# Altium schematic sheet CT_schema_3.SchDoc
size 313 x 200 mm
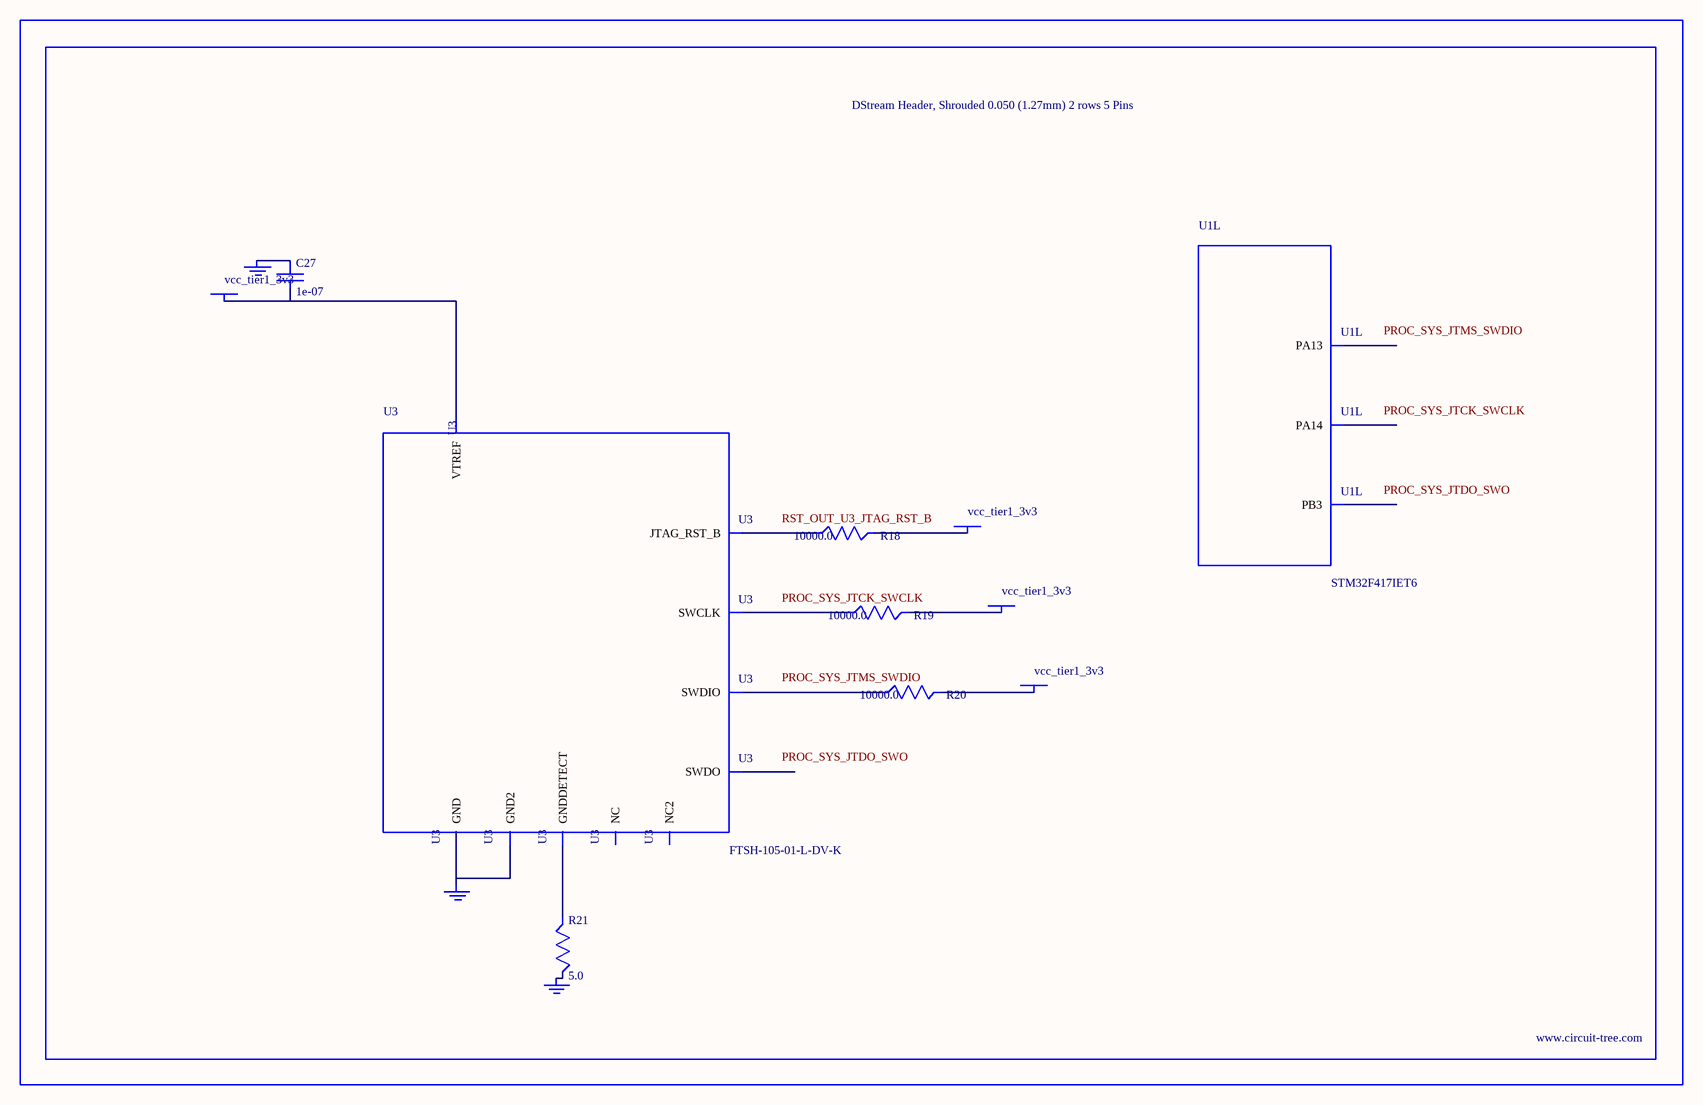
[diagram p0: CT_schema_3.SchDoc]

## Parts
BORDER2  (no value)
C27  1e-07  [C0402]
GND_INSTANCE_2_0  (no value)
GND_INSTANCE_2_1  (no value)
GND_INSTANCE_2_2  (no value)
POWER_INSTANCE_2_0  vcc_tier1_3v3
POWER_INSTANCE_2_1  vcc_tier1_3v3
POWER_INSTANCE_2_2  vcc_tier1_3v3
POWER_INSTANCE_2_3  vcc_tier1_3v3
R18  10000.0  [R0603]
R19  10000.0  [R0603]
R20  10000.0  [R0603]
R21  5.0  [R0603]
U1  STM32F417IET6  [LQFP176]  (part L of 14)
U3  FTSH-105-01-L-DV-K  [SAMTEC_FTSH-105-01-L-DV-K]

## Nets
NetC27_1: C27.1 GND_INSTANCE_2_0.0(GND)
NetC27_2: C27.2 POWER_INSTANCE_2_0.0(PWR) U3.1(VTREF)
NetGND_INSTANCE_2_1_0: GND_INSTANCE_2_1.0(GND) R21.2
NetGND_INSTANCE_2_2_0: GND_INSTANCE_2_2.0(GND) U3.3(GND) U3.5(GND2)
NetPOWER_INSTANCE_2_1_0: POWER_INSTANCE_2_1.0(PWR) R20.2
NetPOWER_INSTANCE_2_2_0: POWER_INSTANCE_2_2.0(PWR) R19.2
NetPOWER_INSTANCE_2_3_0: POWER_INSTANCE_2_3.0(PWR) R18.2
NetR18_1: R18.1 U3.10(JTAG_RST_B)
NetR19_1: R19.1 U3.4(SWCLK)
NetR20_1: R20.1 U3.2(SWDIO)
NetR21_1: R21.1 U3.9(GNDDETECT)

Not connected (* = marked no-connect by the designer): U1 124(PA13) 137(PA14) 161(PB3); U3 6(SWDO) 7(NC) 8(NC2)

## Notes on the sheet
- Labels drawn without touching a wire or pin: PROC_SYS_JTCK_SWCLK, PROC_SYS_JTDO_SWO, PROC_SYS_JTMS_SWDIO, RST_OUT_U3_JTAG_RST_B

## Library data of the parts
BORDER2 = BORDER_PAGE2
C27 = C0402C104K3RACTU
GND_INSTANCE_2_0-GND_INSTANCE_2_2 = GND
POWER_INSTANCE_2_0-POWER_INSTANCE_2_3 = PWR
R18-R20 = RC0603JR-0710KL
R21 = ERJ-3GEYJ5R1V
